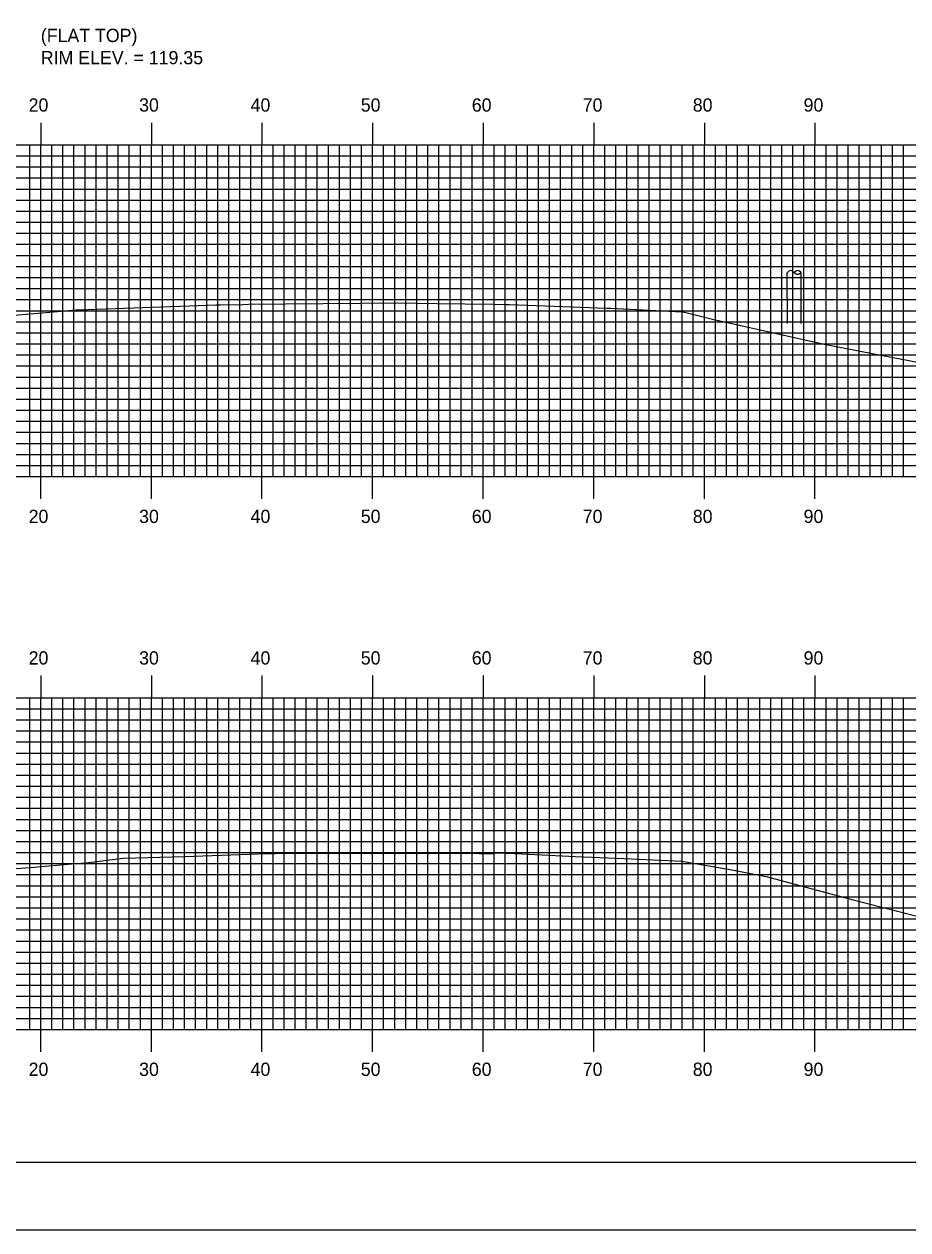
# Model space of a CAD drawing. Extents: x 854681 to 855024, y 366605 to 366825.
# Drawn here: x 854865.1 to 854945, y 366604.9 to 366714 of the extents above; entities that cross this region are included whole.
import ezdxf

# ---------------------------------------------------------------- set-up
doc = ezdxf.new("R2010")
doc.units = 0
for name, color, linetype in [('BORDER', 7, 'Continuous'), ('D_Drainage_Text', 7, 'Continuous'), ('H_V ANNOTATION', 7, 'Continuous'), ('M_Roadway_Centerline', 7, 'Continuous'), ('MAJOR', 7, 'Continuous'), ('MINOR', 7, 'Continuous'), ('PLOT BOUNDARY', 7, 'Continuous'), ('S_Roadway_Centerline', 7, 'Continuous'), ('S_Utilities_Pole_StreetLight', 7, 'Continuous')]:
    doc.layers.add(name, color=color, linetype=linetype)

msp = doc.modelspace()

# ---------------------------------------------------------------- linework, layer by layer
at = {"layer": 'BORDER'}
msp.add_lwpolyline([(854696.96, 366611.06), (855016.96, 366611.06), (855016.96, 366821.06), (854696.96, 366821.06)], close=True, dxfattribs=at)
at = {"layer": 'MAJOR'}
for p, q in [((854866.56, 366705.06), (854866.56, 366703.06)), ((854876.56, 366705.06), (854876.56, 366703.06)), ((854886.56, 366705.06), (854886.56, 366703.06)), ((854896.56, 366705.06), (854896.56, 366703.06)), ((854906.56, 366705.06), (854906.56, 366703.06)), ((854916.56, 366705.06), (854916.56, 366703.06)), ((854926.56, 366705.06), (854926.56, 366703.06)), ((854936.56, 366705.06), (854936.56, 366703.06)), ((854706.56, 366703.06), (854986.56, 366703.06)), ((854706.56, 366703.06), (854986.56, 366703.06)), ((854866.56, 366673.06), (854866.56, 366703.06)), ((854876.56, 366673.06), (854876.56, 366703.06)), ((854886.56, 366673.06), (854886.56, 366703.06)), ((854896.56, 366673.06), (854896.56, 366703.06)), ((854906.56, 366673.06), (854906.56, 366703.06)), ((854916.56, 366673.06), (854916.56, 366703.06)), ((854926.56, 366673.06), (854926.56, 366703.06)), ((854936.56, 366673.06), (854936.56, 366703.06)), ((854706.56, 366698.06), (854986.56, 366698.06)), ((854706.56, 366693.06), (854986.56, 366693.06)), ((854706.56, 366688.06), (854986.56, 366688.06)), ((854706.56, 366683.06), (854986.56, 366683.06)), ((854706.56, 366678.06), (854986.56, 366678.06)), ((854706.56, 366673.06), (854986.56, 366673.06)), ((854706.56, 366673.06), (854986.56, 366673.06)), ((854866.56, 366671.05), (854866.56, 366673.06)), ((854876.56, 366671.05), (854876.56, 366673.06)), ((854886.56, 366671.05), (854886.56, 366673.06)), ((854896.56, 366671.05), (854896.56, 366673.06)), ((854906.56, 366671.05), (854906.56, 366673.06)), ((854916.56, 366671.05), (854916.56, 366673.06)), ((854926.56, 366671.05), (854926.56, 366673.06)), ((854936.56, 366671.05), (854936.56, 366673.06)), ((854866.56, 366655.06), (854866.56, 366653.06)), ((854876.56, 366655.06), (854876.56, 366653.06)), ((854886.56, 366655.06), (854886.56, 366653.06)), ((854896.56, 366655.06), (854896.56, 366653.06)), ((854906.56, 366655.06), (854906.56, 366653.06)), ((854916.56, 366655.06), (854916.56, 366653.06)), ((854926.56, 366655.06), (854926.56, 366653.06)), ((854936.56, 366655.06), (854936.56, 366653.06)), ((854706.56, 366653.06), (854986.56, 366653.06)), ((854706.56, 366653.06), (854986.56, 366653.06)), ((854866.56, 366623.06), (854866.56, 366653.06)), ((854876.56, 366623.06), (854876.56, 366653.06)), ((854886.56, 366623.06), (854886.56, 366653.06)), ((854896.56, 366623.06), (854896.56, 366653.06)), ((854906.56, 366623.06), (854906.56, 366653.06)), ((854916.56, 366623.06), (854916.56, 366653.06)), ((854926.56, 366623.06), (854926.56, 366653.06)), ((854936.56, 366623.06), (854936.56, 366653.06)), ((854706.56, 366648.06), (854986.56, 366648.06)), ((854706.56, 366643.06), (854986.56, 366643.06)), ((854706.56, 366638.06), (854986.56, 366638.06)), ((854706.56, 366633.06), (854986.56, 366633.06)), ((854706.56, 366628.06), (854986.56, 366628.06)), ((854706.56, 366623.06), (854986.56, 366623.06)), ((854706.56, 366623.06), (854986.56, 366623.06)), ((854866.56, 366621.05), (854866.56, 366623.06)), ((854876.56, 366621.05), (854876.56, 366623.06)), ((854886.56, 366621.05), (854886.56, 366623.06)), ((854896.56, 366621.05), (854896.56, 366623.06)), ((854906.56, 366621.05), (854906.56, 366623.06)), ((854916.56, 366621.05), (854916.56, 366623.06)), ((854926.56, 366621.05), (854926.56, 366623.06)), ((854936.56, 366621.05), (854936.56, 366623.06))]:
    msp.add_line(p, q, dxfattribs=at)
at = {"layer": 'MINOR'}
for p, q in [((854865.56, 366673.06), (854865.56, 366703.06)), ((854867.56, 366673.06), (854867.56, 366703.06)), ((854868.56, 366673.06), (854868.56, 366703.06)), ((854869.56, 366673.06), (854869.56, 366703.06)), ((854870.56, 366673.06), (854870.56, 366703.06)), ((854871.56, 366673.06), (854871.56, 366703.06)), ((854872.56, 366673.06), (854872.56, 366703.06)), ((854873.56, 366673.06), (854873.56, 366703.06)), ((854874.56, 366673.06), (854874.56, 366703.06)), ((854875.56, 366673.06), (854875.56, 366703.06)), ((854877.56, 366673.06), (854877.56, 366703.06)), ((854878.56, 366673.06), (854878.56, 366703.06)), ((854879.56, 366673.06), (854879.56, 366703.06)), ((854880.56, 366673.06), (854880.56, 366703.06)), ((854881.56, 366673.06), (854881.56, 366703.06)), ((854882.56, 366673.06), (854882.56, 366703.06)), ((854883.56, 366673.06), (854883.56, 366703.06)), ((854884.56, 366673.06), (854884.56, 366703.06)), ((854885.56, 366673.06), (854885.56, 366703.06)), ((854887.56, 366673.06), (854887.56, 366703.06)), ((854888.56, 366673.06), (854888.56, 366703.06)), ((854889.56, 366673.06), (854889.56, 366703.06)), ((854890.56, 366673.06), (854890.56, 366703.06)), ((854891.56, 366673.06), (854891.56, 366703.06)), ((854892.56, 366673.06), (854892.56, 366703.06)), ((854893.56, 366673.06), (854893.56, 366703.06)), ((854894.56, 366673.06), (854894.56, 366703.06)), ((854895.56, 366673.06), (854895.56, 366703.06)), ((854897.56, 366673.06), (854897.56, 366703.06)), ((854898.56, 366673.06), (854898.56, 366703.06)), ((854899.56, 366673.06), (854899.56, 366703.06)), ((854900.56, 366673.06), (854900.56, 366703.06)), ((854901.56, 366673.06), (854901.56, 366703.06)), ((854902.56, 366673.06), (854902.56, 366703.06)), ((854903.56, 366673.06), (854903.56, 366703.06)), ((854904.56, 366673.06), (854904.56, 366703.06)), ((854905.56, 366673.06), (854905.56, 366703.06)), ((854907.56, 366673.06), (854907.56, 366703.06)), ((854908.56, 366673.06), (854908.56, 366703.06)), ((854909.56, 366673.06), (854909.56, 366703.06)), ((854910.56, 366673.06), (854910.56, 366703.06)), ((854911.56, 366673.06), (854911.56, 366703.06)), ((854912.56, 366673.06), (854912.56, 366703.06)), ((854913.56, 366673.06), (854913.56, 366703.06)), ((854914.56, 366673.06), (854914.56, 366703.06)), ((854915.56, 366673.06), (854915.56, 366703.06)), ((854917.56, 366673.06), (854917.56, 366703.06)), ((854918.56, 366673.06), (854918.56, 366703.06)), ((854919.56, 366673.06), (854919.56, 366703.06)), ((854920.56, 366673.06), (854920.56, 366703.06)), ((854921.56, 366673.06), (854921.56, 366703.06)), ((854922.56, 366673.06), (854922.56, 366703.06)), ((854923.56, 366673.06), (854923.56, 366703.06)), ((854924.56, 366673.06), (854924.56, 366703.06)), ((854925.56, 366673.06), (854925.56, 366703.06)), ((854927.56, 366673.06), (854927.56, 366703.06)), ((854928.56, 366673.06), (854928.56, 366703.06)), ((854929.56, 366673.06), (854929.56, 366703.06)), ((854930.56, 366673.06), (854930.56, 366703.06)), ((854931.56, 366673.06), (854931.56, 366703.06)), ((854932.56, 366673.06), (854932.56, 366703.06)), ((854933.56, 366673.06), (854933.56, 366703.06)), ((854934.56, 366673.06), (854934.56, 366703.06)), ((854935.56, 366673.06), (854935.56, 366703.06)), ((854937.56, 366673.06), (854937.56, 366703.06)), ((854938.56, 366673.06), (854938.56, 366703.06)), ((854939.56, 366673.06), (854939.56, 366703.06)), ((854940.56, 366673.06), (854940.56, 366703.06)), ((854941.56, 366673.06), (854941.56, 366703.06)), ((854942.56, 366673.06), (854942.56, 366703.06)), ((854943.56, 366673.06), (854943.56, 366703.06)), ((854944.56, 366673.06), (854944.56, 366703.06)), ((854706.56, 366702.06), (854986.56, 366702.06)), ((854706.56, 366701.06), (854986.56, 366701.06)), ((854706.56, 366700.06), (854986.56, 366700.06)), ((854706.56, 366699.06), (854986.56, 366699.06)), ((854706.56, 366697.06), (854986.56, 366697.06)), ((854706.56, 366696.06), (854986.56, 366696.06)), ((854706.56, 366695.06), (854986.56, 366695.06)), ((854706.56, 366694.06), (854986.56, 366694.06)), ((854706.56, 366692.06), (854986.56, 366692.06)), ((854706.56, 366691.06), (854986.56, 366691.06)), ((854706.56, 366690.06), (854986.56, 366690.06)), ((854706.56, 366689.06), (854986.56, 366689.06)), ((854706.56, 366687.06), (854986.56, 366687.06)), ((854706.56, 366686.06), (854986.56, 366686.06)), ((854706.56, 366685.06), (854986.56, 366685.06)), ((854706.56, 366684.06), (854986.56, 366684.06)), ((854706.56, 366682.06), (854986.56, 366682.06)), ((854706.56, 366681.06), (854986.56, 366681.06)), ((854706.56, 366680.06), (854986.56, 366680.06)), ((854706.56, 366679.06), (854986.56, 366679.06)), ((854706.56, 366677.06), (854986.56, 366677.06)), ((854706.56, 366676.06), (854986.56, 366676.06)), ((854706.56, 366675.06), (854986.56, 366675.06)), ((854706.56, 366674.06), (854986.56, 366674.06)), ((854865.56, 366623.06), (854865.56, 366653.06)), ((854867.56, 366623.06), (854867.56, 366653.06)), ((854868.56, 366623.06), (854868.56, 366653.06)), ((854869.56, 366623.06), (854869.56, 366653.06)), ((854870.56, 366623.06), (854870.56, 366653.06)), ((854871.56, 366623.06), (854871.56, 366653.06)), ((854872.56, 366623.06), (854872.56, 366653.06)), ((854873.56, 366623.06), (854873.56, 366653.06)), ((854874.56, 366623.06), (854874.56, 366653.06)), ((854875.56, 366623.06), (854875.56, 366653.06)), ((854877.56, 366623.06), (854877.56, 366653.06)), ((854878.56, 366623.06), (854878.56, 366653.06)), ((854879.56, 366623.06), (854879.56, 366653.06)), ((854880.56, 366623.06), (854880.56, 366653.06)), ((854881.56, 366623.06), (854881.56, 366653.06)), ((854882.56, 366623.06), (854882.56, 366653.06)), ((854883.56, 366623.06), (854883.56, 366653.06)), ((854884.56, 366623.06), (854884.56, 366653.06)), ((854885.56, 366623.06), (854885.56, 366653.06)), ((854887.56, 366623.06), (854887.56, 366653.06)), ((854888.56, 366623.06), (854888.56, 366653.06)), ((854889.56, 366623.06), (854889.56, 366653.06)), ((854890.56, 366623.06), (854890.56, 366653.06)), ((854891.56, 366623.06), (854891.56, 366653.06)), ((854892.56, 366623.06), (854892.56, 366653.06)), ((854893.56, 366623.06), (854893.56, 366653.06)), ((854894.56, 366623.06), (854894.56, 366653.06)), ((854895.56, 366623.06), (854895.56, 366653.06)), ((854897.56, 366623.06), (854897.56, 366653.06)), ((854898.56, 366623.06), (854898.56, 366653.06)), ((854899.56, 366623.06), (854899.56, 366653.06)), ((854900.56, 366623.06), (854900.56, 366653.06)), ((854901.56, 366623.06), (854901.56, 366653.06)), ((854902.56, 366623.06), (854902.56, 366653.06)), ((854903.56, 366623.06), (854903.56, 366653.06)), ((854904.56, 366623.06), (854904.56, 366653.06)), ((854905.56, 366623.06), (854905.56, 366653.06)), ((854907.56, 366623.06), (854907.56, 366653.06)), ((854908.56, 366623.06), (854908.56, 366653.06)), ((854909.56, 366623.06), (854909.56, 366653.06)), ((854910.56, 366623.06), (854910.56, 366653.06)), ((854911.56, 366623.06), (854911.56, 366653.06)), ((854912.56, 366623.06), (854912.56, 366653.06)), ((854913.56, 366623.06), (854913.56, 366653.06)), ((854914.56, 366623.06), (854914.56, 366653.06)), ((854915.56, 366623.06), (854915.56, 366653.06)), ((854917.56, 366623.06), (854917.56, 366653.06)), ((854918.56, 366623.06), (854918.56, 366653.06)), ((854919.56, 366623.06), (854919.56, 366653.06)), ((854920.56, 366623.06), (854920.56, 366653.06)), ((854921.56, 366623.06), (854921.56, 366653.06)), ((854922.56, 366623.06), (854922.56, 366653.06)), ((854923.56, 366623.06), (854923.56, 366653.06)), ((854924.56, 366623.06), (854924.56, 366653.06)), ((854925.56, 366623.06), (854925.56, 366653.06)), ((854927.56, 366623.06), (854927.56, 366653.06)), ((854928.56, 366623.06), (854928.56, 366653.06)), ((854929.56, 366623.06), (854929.56, 366653.06)), ((854930.56, 366623.06), (854930.56, 366653.06)), ((854931.56, 366623.06), (854931.56, 366653.06)), ((854932.56, 366623.06), (854932.56, 366653.06)), ((854933.56, 366623.06), (854933.56, 366653.06)), ((854934.56, 366623.06), (854934.56, 366653.06)), ((854935.56, 366623.06), (854935.56, 366653.06)), ((854937.56, 366623.06), (854937.56, 366653.06)), ((854938.56, 366623.06), (854938.56, 366653.06)), ((854939.56, 366623.06), (854939.56, 366653.06)), ((854940.56, 366623.06), (854940.56, 366653.06)), ((854941.56, 366623.06), (854941.56, 366653.06)), ((854942.56, 366623.06), (854942.56, 366653.06)), ((854943.56, 366623.06), (854943.56, 366653.06)), ((854944.56, 366623.06), (854944.56, 366653.06)), ((854706.56, 366652.06), (854986.56, 366652.06)), ((854706.56, 366651.06), (854986.56, 366651.06)), ((854706.56, 366650.06), (854986.56, 366650.06)), ((854706.56, 366649.06), (854986.56, 366649.06)), ((854706.56, 366647.06), (854986.56, 366647.06)), ((854706.56, 366646.06), (854986.56, 366646.06)), ((854706.56, 366645.06), (854986.56, 366645.06)), ((854706.56, 366644.06), (854986.56, 366644.06)), ((854706.56, 366642.06), (854986.56, 366642.06)), ((854706.56, 366641.06), (854986.56, 366641.06)), ((854706.56, 366640.06), (854986.56, 366640.06)), ((854706.56, 366639.06), (854986.56, 366639.06)), ((854706.56, 366637.06), (854986.56, 366637.06)), ((854706.56, 366636.06), (854986.56, 366636.06)), ((854706.56, 366635.06), (854986.56, 366635.06)), ((854706.56, 366634.06), (854986.56, 366634.06)), ((854706.56, 366632.06), (854986.56, 366632.06)), ((854706.56, 366631.06), (854986.56, 366631.06)), ((854706.56, 366630.06), (854986.56, 366630.06)), ((854706.56, 366629.06), (854986.56, 366629.06)), ((854706.56, 366627.06), (854986.56, 366627.06)), ((854706.56, 366626.06), (854986.56, 366626.06)), ((854706.56, 366625.06), (854986.56, 366625.06)), ((854706.56, 366624.06), (854986.56, 366624.06))]:
    msp.add_line(p, q, dxfattribs=at)
at = {"layer": 'PLOT BOUNDARY'}
msp.add_lwpolyline([(854680.77, 366604.94), (855020.77, 366604.94), (855020.77, 366824.94), (854680.77, 366824.94)], close=True, dxfattribs=at)
at = {"layer": 'S_Roadway_Centerline'}
for points in [[(854860.89, 366687.37), (854867.04, 366687.9), (854869.76, 366688.13), (854869.97, 366688.14), (854881.62, 366688.55), (854882.4, 366688.58), (854882.65, 366688.59), (854882.81, 366688.59), (854884.83, 366688.63), (854885.34, 366688.64), (854898.77, 366688.78), (854902.37, 366688.71), (854907.49, 366688.65), (854908.51, 366688.63), (854908.94, 366688.61), (854917.74, 366688.29), (854918.03, 366688.28), (854923.96, 366687.98), (854924.57, 366687.95), (854924.75, 366687.92), (854927.29, 366687.3), (854937.38, 366685.04), (854949.42, 366682.71)], [(854850.08, 366636.54), (854865.93, 366637.73), (854869.72, 366638.06), (854870.66, 366638.12), (854874.02, 366638.56), (854879.56, 366638.71), (854885.41, 366638.92), (854887.07, 366638.96), (854887.74, 366638.98), (854887.88, 366638.99), (854888.85, 366639.01), (854906.2, 366638.98), (854907.47, 366638.97), (854907.79, 366639.03), (854909.46, 366638.97), (854914.92, 366638.71), (854919.31, 366638.53), (854922.61, 366638.37), (854924.5, 366638.27), (854928.9, 366637.54), (854932.15, 366636.9), (854940.01, 366634.77), (854946.6, 366633.11)]]:
    msp.add_lwpolyline(points, dxfattribs=at)
at = {"layer": 'S_Utilities_Pole_StreetLight'}
for p, q in [((854934.06, 366686.9), (854934.05, 366691.52)), ((854934.06, 366691.52), (854934.21, 366691.63)), ((854934.52, 366691.63), (854934.68, 366691.52)), ((854934.84, 366691.63), (854934.68, 366691.52)), ((854934.68, 366691.52), (854934.84, 366691.41)), ((854935.31, 366691.52), (854935.15, 366691.63)), ((854935.15, 366691.41), (854935.31, 366691.52)), ((854935.31, 366686.9), (854935.3, 366691.52))]:
    msp.add_line(p, q, dxfattribs=at)
for centre, start, end in [((854934.37, 366691.41), 90, 125.2644), ((854934.37, 366691.41), 54.7356, 90), ((854934.99, 366691.41), 90, 125.2644), ((854934.99, 366691.41), 54.7356, 90), ((854934.99, 366691.63), 234.7356, 270), ((854934.99, 366691.63), 270, 305.2644)]:
    msp.add_arc(centre, 0.271, start, end, dxfattribs=at)

# ---------------------------------------------------------------- texts
at = {"layer": 'D_Drainage_Text'}
for s, p in [('(FLAT TOP) ', (854866.56, 366712.35)), ('RIM ELEV. = 119.35', (854866.56, 366710.34))]:
    msp.add_text(s, height=1.2, dxfattribs=at).set_placement(p)
at = {"layer": 'H_V ANNOTATION'}
for s, p in [('20', (854865.46, 366706.06)), ('30', (854875.45, 366706.06)), ('40', (854885.53, 366706.06)), ('50', (854895.49, 366706.06)), ('60', (854905.53, 366706.06)), ('70', (854915.56, 366706.06)), ('80', (854925.51, 366706.06)), ('90', (854935.53, 366706.06)), ('20', (854865.46, 366668.86)), ('30', (854875.45, 366668.86)), ('40', (854885.53, 366668.86)), ('50', (854895.49, 366668.86)), ('60', (854905.53, 366668.86)), ('70', (854915.56, 366668.86)), ('80', (854925.51, 366668.86)), ('90', (854935.53, 366668.86)), ('20', (854865.46, 366656.06)), ('30', (854875.45, 366656.06)), ('40', (854885.53, 366656.06)), ('50', (854895.49, 366656.06)), ('60', (854905.53, 366656.06)), ('70', (854915.56, 366656.06)), ('80', (854925.51, 366656.06)), ('90', (854935.53, 366656.06)), ('20', (854865.46, 366618.86)), ('30', (854875.45, 366618.86)), ('40', (854885.53, 366618.86)), ('50', (854895.49, 366618.86)), ('60', (854905.53, 366618.86)), ('70', (854915.56, 366618.86)), ('80', (854925.51, 366618.86)), ('90', (854935.53, 366618.86))]:
    msp.add_text(s, height=1.2, dxfattribs=at).set_placement(p)
at = {"layer": 'M_Roadway_Centerline'}
for s, p in [('C', (854882.64, 366688.59)), ('L', (854882.65, 366688.58)), ('C', (854908.51, 366688.63)), ('L', (854908.51, 366688.62)), ('C', (854887.74, 366638.98)), ('L', (854887.74, 366638.97)), ('C', (854907.78, 366639.03)), ('L', (854907.79, 366639.02))]:
    msp.add_text(s, height=0.0146, dxfattribs=at).set_placement(p)

doc.saveas('drawing.dxf')
